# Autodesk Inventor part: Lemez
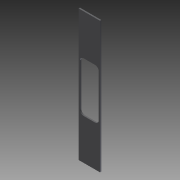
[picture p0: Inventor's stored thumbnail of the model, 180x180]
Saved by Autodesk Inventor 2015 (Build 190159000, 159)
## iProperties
Created: 2013-02
Part Number: Lemez
Material: Generic
Document SubType Name: Modeling
Designer: Marci
Density: 1 g/cm^3
Appearance: Gray
Author: Marci
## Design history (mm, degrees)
sketch "Sketch1"
  geometry: L1 (0, 0)-(0, 3.5); L2 (0, 3.5)-(55, 3.5); L3 (55, 3.5)-(55, 0); L4 (55, 0)-(0, 0)
  constraints: 8 end point, 2 perpendicular, 1 parallel, 1 vertical
  dimensions: "d0" = 3.5 distance of L1.start L1.end; "d1" = 55 distance of L1.end L2.end
extrude "Extrusion1" new body sketch "Sketch1" distance "d2" = 339; taper "d3" = 0 deg
sketch "Sketch2"
  geometry: L1 (13, 234)-(42, 234); L2 (52, 224)-(52, 115); L3 (42, 105)-(13, 105); L4 (3, 115)-(3, 224); A1 r 10 centre (13, 224) between (13, 234) and (3, 224); A2 r 10 centre (42, 224) between (52, 224) and (42, 234); A3 r 10 centre (13, 115) between (3, 115) and (13, 105); A4 r 10 centre (42, 115) between (42, 105) and (52, 115); 3 further points
  constraints: 8 end point, 8 point on circle, 8 tangent, 6 point on line, 4 centre point, 3 equal radius
  dimensions: "d11" = 49 distance of point (3, 234) point (52, 234); "d12" = 129 distance of point (52, 234) point (52, 105); "d13" = 10 radius of A1
extrude "Extrusion2" cut sketch "Sketch2" distance "d14" = 10; taper "d15" = 0 deg
body "Solid1"
